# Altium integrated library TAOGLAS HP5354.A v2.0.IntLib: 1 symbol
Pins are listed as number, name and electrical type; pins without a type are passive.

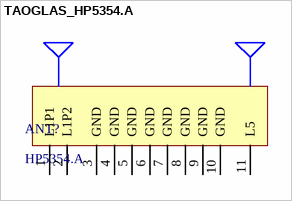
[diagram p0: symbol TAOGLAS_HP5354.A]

## TAOGLAS_HP5354.A
designator ANT?, comment HP5354.A
Low Profile Multi-Band GNSS L1/L5 Patch Antenna; ComponentLibStatus: Created; MFG: Taoglas; Temp_High: +85C; Temp_Low: -40C
footprint TAOGLAS_HP5354.A (Low Profile Multi-Band GNSS L1/L5 Patch Antenna)
pins: 1 L1P1, 2 L1P2, 3 GND, 4 GND, 5 GND, 6 GND, 7 GND, 8 GND, 9 GND, 10 GND, 11 L5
